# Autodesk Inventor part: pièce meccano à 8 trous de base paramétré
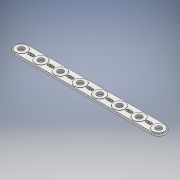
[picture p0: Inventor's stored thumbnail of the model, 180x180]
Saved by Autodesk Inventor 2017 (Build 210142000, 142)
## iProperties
Part Number: pièce meccano à 8 trous de base paramétré
Material: Plastique PC/ABS
Document SubType Name: Modeling
Designer: ficho
Density: 0.357273 g/cm^3
Appearance: Lisse - Blanc
Author: ficho
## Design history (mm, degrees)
sketch "Esquisse1"
  geometry: L1 (220.5, 11)-(0, 11); L2 (220.5, -11)-(0, -11); A1 r 11 centre (0, 0) between (0, 11) and (0, -11); A2 r 11 centre (220.5, 0) between (220.5, -11) and (220.5, 11); 1 further point
  constraints: 4 end point, 4 point on circle, 4 tangent, 2 centre point, 1 coincident
  dimensions: "d0" = 22 diameter of A1 (= largeur); "d1" = 22 diameter of A2 (= largeur); "d2" = 242.5 dimension on A2 A1 (= long)
extrude "Extrusion1" new body sketch "Esquisse1" distance "d3" = 3.8 (= ep); taper "d4" = 0 deg
fillet "Congé1" dims "d5" = 0.5
fillet "Congé2" dims "d6" = 0.5
sketch "Esquisse2"
  geometry: C1 r 9.15 at (0, 0); 1 further point
  constraints: 1 centre point, 1 coincident
  dimensions: "d14" = 18.3 diameter of C1
extrude "Extrusion2" join sketch "Esquisse2" distance "d15" = 0.25; taper "d16" = 0 deg
node "Plan de construction1"
mirror "Symétrie1"
fillet "Congé4" dims "d19" = 0.25
sketch "Esquisse4"
  geometry: 1 further point
hole "Perçage2" sketch "Esquisse4" at (0, 0) diameter "d20" = 9.5 (= alesage); stored, may be unused: countersink angle "d24" = 90 deg, drill point angle "d26" = 118 deg; dims "d21" = 6, "d22" = 4, "d23" = 2, "d25" = 8
pattern_linear "Réseau rectangulaire1" dims "d29" = 31.5 (= repet)
sketch "Esquisse5"
  geometry: L1 (18.75, 2)-(12.75, 2); L2 (18.75, -2)-(12.75, -2); C1 r 4.75 at (31.5, 0) reference; A1 r 2 centre (18.75, 0) between (18.75, -2) and (18.75, 2); A2 r 2 centre (12.75, 0) between (12.75, 2) and (12.75, -2); 1 further point
  constraints: 4 end point, 4 point on circle, 4 tangent, 2 centre point
  dimensions: "d30" = 4 diameter of A1; "d31" = 4 diameter of A2; "d32" = 6 distance of A2.centre A1.centre; "d33" = 12.75 distance of A2.centre point (0, 0)
extrude "Extrusion3" cut sketch "Esquisse5" stored distance "d35" = 0.25; taper "d36" = 0 deg
fillet "Congé5" dims "d37" = 0.25
pattern_linear "Réseau rectangulaire2" dims "d40" = 31.5 (= repet)
node "Solide1"
other parameters: "largeur" = 22 [user parameter; used in 2 equation terms], "long" = 242.5 [user parameter; used in 1 equation term], "ep" = 3.8 [user parameter; used in 2 equation terms], "alesage" = 9.5 [user parameter; used in 1 equation term], "d18" = -1.9 (= -0.5 x ep), "repet" = 31.5 [user parameter; used in 2 equation terms]
